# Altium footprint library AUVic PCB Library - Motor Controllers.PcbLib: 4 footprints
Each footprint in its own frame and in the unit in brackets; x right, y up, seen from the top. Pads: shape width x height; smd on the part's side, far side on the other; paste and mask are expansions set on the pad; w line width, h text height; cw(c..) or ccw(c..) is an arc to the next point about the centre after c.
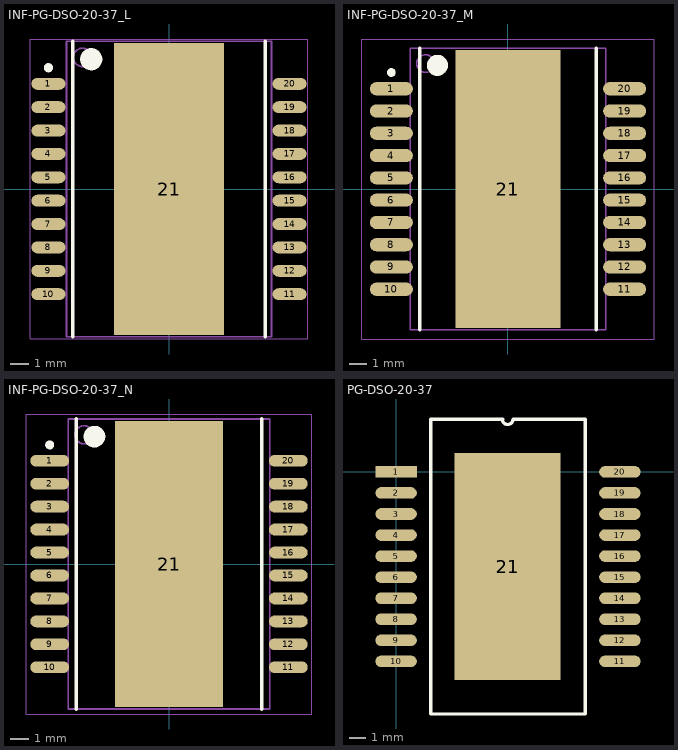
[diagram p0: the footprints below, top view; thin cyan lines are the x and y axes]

## INF-PG-DSO-20-37_L [mm] "SOP, 20-Leads, Body 15.9x11mm, Pitch 1.27mm, Thermal Pad 15.84x6mm, IPC High Density"
height 3.5
pads (21):
  oval 1.85x0.65 smd: 1(-6.55,5.715) 2(-6.55,4.445) 3(-6.55,3.175) 4(-6.55,1.905) 5(-6.55,0.635) 6(-6.55,-0.635) 7(-6.55,-1.905) 8(-6.55,-3.175) 9(-6.55,-4.445) 10(-6.55,-5.715) 11(6.55,-5.715) 12(6.55,-4.445) 13(6.55,-3.175) 14(6.55,-1.905) 15(6.55,-0.635) 16(6.55,0.635) 17(6.55,1.905) 18(6.55,3.175) 19(6.55,4.445) 20(6.55,5.715)
  rect 6x15.84 smd: 21(0,0)
Top Overlay:
  circle w0.25: c-6.55,6.59 r0.125
  circle w0.6: c-4.225,7.05 r0.3
  lines w0.2: -5.225,-8.025 -5.225,8.025 ; 5.225,-8.025 5.225,8.025
Mechanical 13:
  circle w0.1: c-4.7,7.15 r0.5
  lines w0.1: -5.575,-8.025 -5.575,8.025 5.575,8.025 5.575,-8.025 -5.575,-8.025
Mechanical 15:
  lines w0.05: -7.55,-8.15 -7.55,8.15 7.55,8.15 7.55,-8.15 -7.55,-8.15
  lines w0.1: -0.5,0 0.5,0 ; 0,-0.5 0,0.5
3D body: height 3.5, standoff 0, extent -5.575,-8.025 5.575,8.025

## INF-PG-DSO-20-37_M [mm] "SOP, 20-Leads, Body 15.9x11mm, Pitch 1.27mm, Thermal Pad 15.84x6mm, IPC Low Density"
height 3.5
pads (21):
  oval 2.45x0.75 smd: 1(-6.65,5.715) 2(-6.65,4.445) 3(-6.65,3.175) 4(-6.65,1.905) 5(-6.65,0.635) 6(-6.65,-0.635) 7(-6.65,-1.905) 8(-6.65,-3.175) 9(-6.65,-4.445) 10(-6.65,-5.715) 11(6.65,-5.715) 12(6.65,-4.445) 13(6.65,-3.175) 14(6.65,-1.905) 15(6.65,-0.635) 16(6.65,0.635) 17(6.65,1.905) 18(6.65,3.175) 19(6.65,4.445) 20(6.65,5.715)
  rect 6x15.84 smd: 21(0,0)
Top Overlay:
  circle w0.6: c-4.025,7.05 r0.3
  circle w0.25: c-6.65,6.64 r0.125
  lines w0.2: -5.025,-8.025 -5.025,8.025 ; 5.025,-8.025 5.025,8.025
Mechanical 13:
  circle w0.1: c-4.7,7.15 r0.5
  lines w0.1: -5.575,-8.025 5.575,-8.025 5.575,8.025 -5.575,8.025 -5.575,-8.025
Mechanical 15:
  lines w0.05: -8.35,-8.55 8.35,-8.55 8.35,8.55 -8.35,8.55 -8.35,-8.55
  lines w0.1: -0.5,0 0.5,0 ; 0,-0.5 0,0.5
3D body: height 3.5, standoff 0, extent -5.575,-8.025 5.575,8.025

## INF-PG-DSO-20-37_N [mm] "SOP, 20-Leads, Body 15.9x11mm, Pitch 1.27mm, Thermal Pad 15.84x6mm, IPC Medium Density"
height 3.5
pads (21):
  oval 2.15x0.65 smd: 1(-6.6,5.715) 2(-6.6,4.445) 3(-6.6,3.175) 4(-6.6,1.905) 5(-6.6,0.635) 6(-6.6,-0.635) 7(-6.6,-1.905) 8(-6.6,-3.175) 9(-6.6,-4.445) 10(-6.6,-5.715) 11(6.6,-5.715) 12(6.6,-4.445) 13(6.6,-3.175) 14(6.6,-1.905) 15(6.6,-0.635) 16(6.6,0.635) 17(6.6,1.905) 18(6.6,3.175) 19(6.6,4.445) 20(6.6,5.715)
  rect 6x15.84 smd: 21(0,0)
Top Overlay:
  circle w0.25: c-6.6,6.59 r0.125
  circle w0.6: c-4.125,7.05 r0.3
  lines w0.2: -5.125,-8.025 -5.125,8.025 ; 5.125,-8.025 5.125,8.025
Mechanical 13:
  circle w0.1: c-4.7,7.15 r0.5
  lines w0.1: -5.575,-8.025 -5.575,8.025 5.575,8.025 5.575,-8.025 -5.575,-8.025
Mechanical 15:
  lines w0.05: -7.9,-8.3 -7.9,8.3 7.9,8.3 7.9,-8.3 -7.9,-8.3
  lines w0.1: -0.5,0 0.5,0 ; 0,-0.5 0,0.5
3D body: height 3.5, standoff 0, extent -5.575,-8.025 5.575,8.025

## PG-DSO-20-37 [mm]
pads (21):
  rect 2.5x0.7 smd: 1(0,0)
  oval 2.5x0.7 smd: 2(0,-1.27) 3(0,-2.54) 4(0,-3.81) 5(0,-5.08) 6(0,-6.35) 7(0,-7.62) 8(0,-8.89) 9(0,-10.16) 10(0,-11.43) 11(13.5,-11.43) 12(13.5,-10.16) 13(13.5,-8.89) 14(13.5,-7.62) 15(13.5,-6.35) 16(13.5,-5.08) 17(13.5,-3.81) 18(13.5,-2.54) 19(13.5,-1.27) 20(13.5,0)
  rect 6.4x13.7 smd: 21(6.731,-5.715)
Top Overlay:
  lines w0.2: 6.413,3.175 ccw(c6.731,3.175) 7.048,3.175 ; 6.432,3.175 2.085,3.175 2.085,-14.605 11.415,-14.605 11.415,3.175 7.067,3.175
